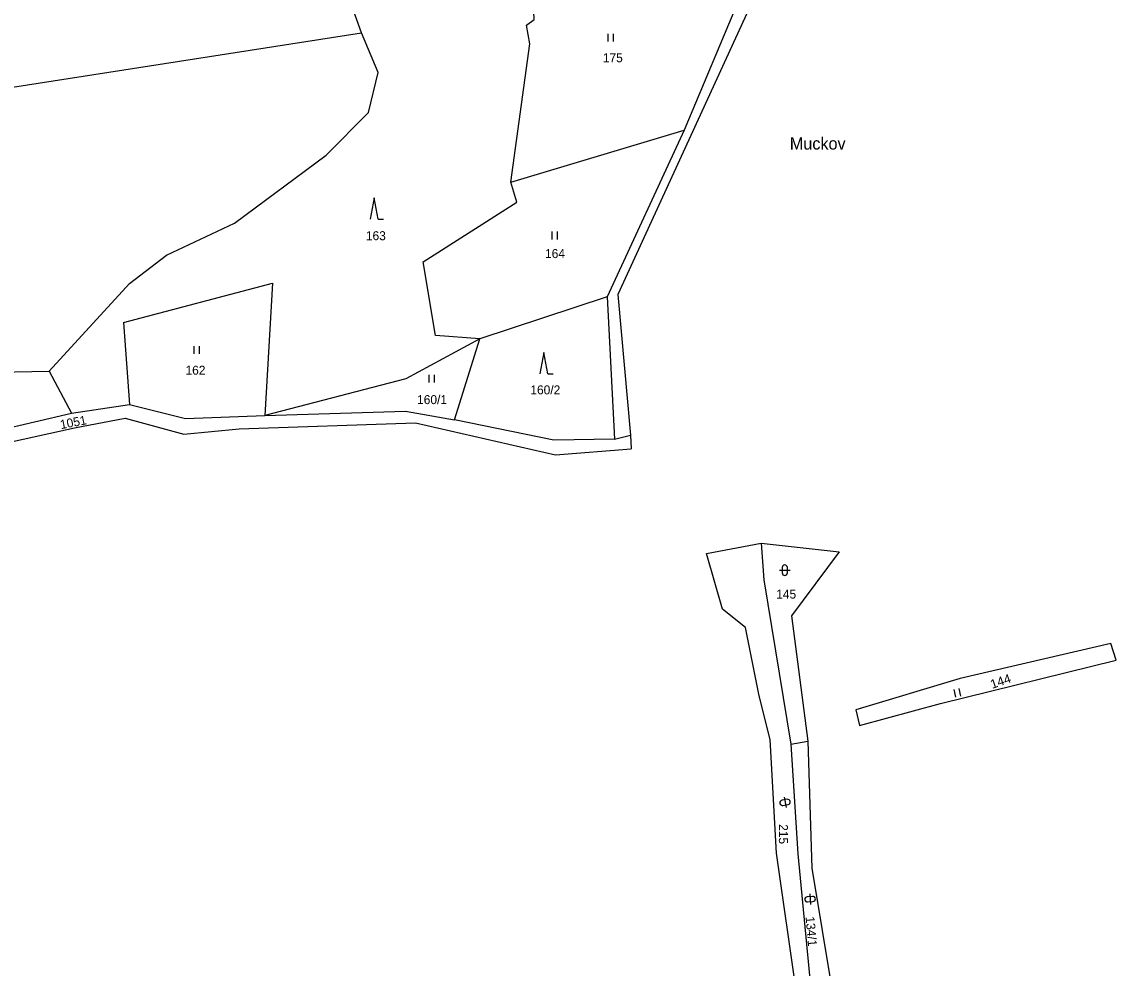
# Model space of a CAD drawing. Extents: x -744132 to -742433, y -984679 to -982287.
# Drawn here: x -743040.9 to -742833, y -984240 to -984060.3 of the extents above; entities that cross this region are included whole.
import ezdxf

# ---------------------------------------------------------------- set-up
doc = ezdxf.new("R2010")
doc.units = 0
doc.header["$LTSCALE"] = 0.68
for name, color, linetype, lineweight in [('1', 7, 'Continuous', 25), ('3', 7, 'Continuous', 25), ('7', 7, 'Continuous', 13)]:
    doc.layers.add(name, color=color, linetype=linetype, lineweight=lineweight)
doc.layers.add('2', color=7, linetype='Continuous')

msp = doc.modelspace()

# ---------------------------------------------------------------- linework, layer by layer
at = {"layer": '1'}
for p, q in [((-742901.65, -984048.94), (-742915.06, -984080.88)), ((-742899.55, -984050.85), (-742927.66, -984112.13)), ((-742976.37, -984062.42), (-742978.8, -984055.59)), ((-743064.26, -984076.08), (-742976.37, -984062.42)), ((-742973.22, -984069.92), (-742976.37, -984062.42)), ((-742944.4, -984064.51), (-742945.05, -984060.92)), ((-742947.98, -984090.77), (-742944.4, -984064.51)), ((-742975.06, -984077.51), (-742973.22, -984069.92)), ((-742983.09, -984085.63), (-742975.06, -984077.51)), ((-742947.98, -984090.77), (-742915.06, -984080.88)), ((-742915.06, -984080.88), (-742929.68, -984112.57)), ((-743000.54, -984098.58), (-742983.09, -984085.63)), ((-742946.89, -984094.55), (-742947.98, -984090.77)), ((-742964.66, -984105.89), (-742946.89, -984094.55)), ((-743013.4, -984104.63), (-743000.54, -984098.58)), ((-743020.44, -984110.02), (-743013.4, -984104.63)), ((-742962.34, -984119.9), (-742964.66, -984105.89)), ((-743035.75, -984126.63), (-743020.44, -984110.02)), ((-743021.59, -984117.42), (-742993.29, -984109.96)), ((-742993.29, -984109.96), (-742994.76, -984135.06)), ((-742927.66, -984112.13), (-742925.27, -984138.83)), ((-742929.68, -984112.57), (-742953.92, -984120.55)), ((-742929.68, -984112.57), (-742928.29, -984139.55)), ((-743021.59, -984117.42), (-743020.45, -984132.97)), ((-742953.92, -984120.55), (-742967.96, -984128.14)), ((-742953.92, -984120.55), (-742962.34, -984119.9)), ((-742958.72, -984135.91), (-742953.92, -984120.55)), ((-743049.17, -984126.95), (-743035.75, -984126.63)), ((-743035.75, -984126.63), (-743031.51, -984134.65)), ((-742967.96, -984128.14), (-742994.76, -984135.06)), ((-743031.51, -984134.65), (-743020.45, -984132.97)), ((-743020.45, -984132.97), (-743009.8, -984135.68)), ((-743074.32, -984144.64), (-743031.51, -984134.65)), ((-743009.8, -984135.68), (-742994.76, -984135.06)), ((-742994.76, -984135.06), (-742968.05, -984134.23)), ((-742968.05, -984134.23), (-742958.72, -984135.91)), ((-743091.1, -984150.78), (-743030.9, -984137.42)), ((-743030.9, -984137.42), (-743021.27, -984135.58)), ((-743021.27, -984135.58), (-743010.12, -984138.6)), ((-742999.6, -984137.59), (-742966.15, -984136.46)), ((-742966.15, -984136.46), (-742939.53, -984142.53)), ((-742939.85, -984139.78), (-742958.72, -984135.91)), ((-743010.12, -984138.6), (-742999.6, -984137.59)), ((-742928.29, -984139.55), (-742939.85, -984139.78)), ((-742928.29, -984139.55), (-742925.27, -984138.83)), ((-742925.27, -984138.83), (-742925.17, -984141.39)), ((-742939.53, -984142.53), (-742925.17, -984141.39)), ((-742910.82, -984161.32), (-742900.47, -984159.34)), ((-742900.47, -984159.34), (-742899.94, -984166.32)), ((-742900.47, -984159.34), (-742885.64, -984160.96)), ((-742907.81, -984171.84), (-742910.82, -984161.32)), ((-742885.64, -984160.96), (-742894.69, -984173.15)), ((-742899.94, -984166.32), (-742894.84, -984197.48)), ((-742903.41, -984175.37), (-742907.81, -984171.84)), ((-742894.69, -984173.15), (-742891.55, -984196.93)), ((-742900.82, -984188.3), (-742903.41, -984175.37)), ((-742834, -984178.37), (-742862.66, -984185.05)), ((-742833.01, -984181.57), (-742834, -984178.37)), ((-742866.37, -984189.79), (-742833.01, -984181.57)), ((-742862.66, -984185.05), (-742882.45, -984190.99)), ((-742898.71, -984196.62), (-742900.82, -984188.3)), ((-742882.45, -984190.99), (-742881.75, -984193.97)), ((-742881.75, -984193.97), (-742866.37, -984189.79)), ((-742897.56, -984218.2), (-742898.71, -984196.62)), ((-742894.84, -984197.48), (-742891.55, -984196.93)), ((-742894.84, -984197.48), (-742893.47, -984218.33)), ((-742891.55, -984196.93), (-742890.85, -984221.06)), ((-742892.96, -984249.85), (-742897.56, -984218.2)), ((-742893.47, -984218.33), (-742890.83, -984245.87)), ((-742890.85, -984221.06), (-742883.73, -984263.4))]:
    msp.add_line(p, q, dxfattribs=at)
msp.add_lwpolyline([(-742945.05, -984060.92), (-742943.58, -984059.88), (-742944.22, -984045.71)], dxfattribs=at)
at = {"layer": '3'}
for p, q in [((-742929.531, -984064.07), (-742929.531, -984062.57)), ((-742928.53, -984064.07), (-742928.53, -984062.57)), ((-742973.22, -984097.77), (-742972.224, -984097.77)), ((-742940.161, -984101.64), (-742940.161, -984100.14)), ((-742939.16, -984101.64), (-742939.16, -984100.14)), ((-743008.151, -984123.4), (-743008.151, -984121.9)), ((-743007.15, -984123.4), (-743007.15, -984121.9)), ((-742963.541, -984128.83), (-742963.541, -984127.33)), ((-742962.54, -984128.83), (-742962.54, -984127.33)), ((-742940.98, -984127.14), (-742939.984, -984127.14)), ((-742896.961, -984164.471), (-742894.959, -984164.471)), ((-742896.461, -984163.971), (-742896.461, -984164.972)), ((-742895.459, -984164.972), (-742895.459, -984163.971)), ((-742863.468, -984188.585), (-742863.805, -984187.123)), ((-742862.492, -984188.36), (-742862.83, -984186.898)), ((-742895.49, -984207.977), (-742896.476, -984208.151)), ((-742896.07, -984207.571), (-742895.722, -984209.542)), ((-742896.302, -984209.136), (-742895.316, -984208.963)), ((-742890.689, -984226.406), (-742891.688, -984226.476)), ((-742891.223, -984225.942), (-742891.084, -984227.939)), ((-742891.618, -984227.475), (-742890.619, -984227.405))]:
    msp.add_line(p, q, dxfattribs=at)
for points in [[(-742973.22, -984097.77), (-742973.97, -984093.77), (-742974.72, -984097.77)], [(-742940.98, -984127.14), (-742941.73, -984123.14), (-742942.48, -984127.14)]]:
    msp.add_lwpolyline(points, dxfattribs=at)
for centre, start, end in [((-742895.96, -984163.9709), 0, 180), ((-742895.96, -984164.9709), 180, 359.98789), ((-742896.3885, -984208.6433), 100, 279.98789), ((-742895.4037, -984208.4697), 280, 100), ((-742891.6521, -984226.9752), 94, 273.98789), ((-742890.6546, -984226.9054), 274, 94)]:
    msp.add_arc(centre, 0.5, start, end, dxfattribs=at)

# ---------------------------------------------------------------- texts
at = {"layer": '2'}
for s, p in [('175', (-742930.53, -984067.995)), ('163', (-742975.55, -984101.785)), ('164', (-742941.51, -984105.175)), ('162', (-743009.82, -984127.325)), ('160/1', (-742965.82, -984132.915)), ('160/2', (-742944.3, -984131.065)), ('145', (-742897.59, -984169.855))]:
    msp.add_text(s, height=1.7, dxfattribs=at).set_placement(p)
for s, rotation, p in [('1051', 11, (-743033.468, -984137.687)), ('215', 270, (-742897.075, -984212.69)), ('134/1', 275, (-742892.013, -984230.297))]:
    msp.add_text(s, height=1.7, rotation=rotation, dxfattribs=at).set_placement(p)
at = {"layer": '2', "width": 1.05}
msp.add_text('144', height=1.7, rotation=19, dxfattribs=at).set_placement((-742856.571, -984187.011))
at = {"layer": '7'}
msp.add_text('Muckov', height=2.3, dxfattribs=at).set_placement((-742895, -984084.575))

doc.saveas('drawing.dxf')
